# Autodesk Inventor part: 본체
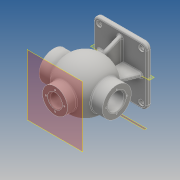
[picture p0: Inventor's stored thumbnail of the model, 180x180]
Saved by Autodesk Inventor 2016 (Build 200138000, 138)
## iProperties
Created: 2017-01
Part Number: 본체
Material: 일반
Document SubType Name: Modeling
Designer: Administrator
Density: 1 g/cm^3
Appearance: 기본값
Author: Administrator
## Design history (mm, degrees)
sketch "스케치1"
  geometry: L1 (57.5, 62.5)-(-57.5, 62.5); L2 (-57.5, 62.5)-(-57.5, -62.5); L3 (-57.5, -62.5)-(57.5, -62.5); L4 (57.5, -62.5)-(57.5, 62.5); L5 (57.5, 62.5)-(-57.5, -62.5); L6 (-57.5, 62.5)-(57.5, -62.5); 1 further point
  constraints: 12 end point, 2 midpoint, 2 parallel, 1 horizontal, 1 perpendicular
  dimensions: "d0" = 125 distance between parallel lines of L3 L1; "d1" = 115 distance between parallel lines of L2 L4
extrude "돌출1" new body sketch "스케치1" distance "d2" = 10; taper "d3" = 0 deg
fillet "모깎기2" dims "d5" = 3
fillet "모깎기3" dims "d6" = 12
node "작업 평면1"
sketch "스케치5"
  geometry: L1 (113.5, -75)-(-22.5, -75); L2 (113.5, -75)-(113.5, -106); L3 (-22.5, -75)-(-22.5, -106); L4 (45.5, 0)-(45.5, -185.881); L5 (113.5, -106)-(88.488, -106); L6 (-22.5, -106)-(2.512, -106); L7 (113.5, -92.5)-(84.778, -92.5); L8 (-22.5, -92.5)-(-6.5, -92.5); L9 (-6.5, -92.5)-(-6.5, -93.5); L10 (-6.5, -93.5)-(-4.75, -93.5); L11 (-4.75, -93.5)-(-4.75, -92.5); L12 (-4.75, -92.5)-(6.222, -92.5); L13 (0, 10)-(91, 10) reference; A1 r 53 centre (45.5, -75) between (2.512, -106) and (88.488, -106); A2 r 43 centre (45.5, -75) between (6.222, -92.5) and (84.778, -92.5)
  constraints: 24 end point, 5 horizontal, 4 point on circle, 4 point on line, 3 perpendicular, 3 vertical, 2 centre point, 1 coincident, 1 midpoint
  dimensions: "d22" = 136 distance between parallel lines of L3 L2; "d27" = 31 distance from line of L2.end L1; "d30" = 53 radius of A1; "d31" = 43 radius of A2; "d32" = 16 distance between parallel lines of L9 L3; "d33" = 17.5 distance between parallel lines of L1 L8; "d34" = 18.5 distance between parallel lines of L1 L10; "d35" = 17.5 distance between parallel lines of L7 L1; "d36" = 17.5 distance from line of L1 L12.end; "d37" = 31 distance between parallel lines of L6 L1; "d38" = 1.75 distance between parallel lines of L11 L9; "d39" = 85 distance between parallel lines of L13 L1
revolve "회전1" sketch "스케치5" stored, may be unused: angle "d40" = 90 deg
sketch "스케치6" dims "d41" = 48
  geometry: 3 further points
  constraints: 1 vertical alignment, 2 other
hole "구멍2" sketch "스케치6" at (0, -24) diameter "d42" = 3.242; stored, may be unused: countersink angle "d46" = 90 deg, drill point angle "d48" = 118 deg; dims "d43" = 16, "d44" = 12, "d45" = 3, "d47" = 19
node "작업 평면2"
sketch "스케치8"
  geometry: C1 r 27 at (0, 0); 1 further point
  constraints: 1 centre point, 1 coincident
  dimensions: "d61" = 54 diameter of C1
extrude "돌출2" join sketch "스케치8" stored distance "d62" = 10; taper "d63" = 0 deg
sketch "스케치9"
  geometry: C1 r 13 at (0, 0); 1 further point
  constraints: 1 centre point, 1 coincident
  dimensions: "d64" = 26 diameter of C1
extrude "돌출3" cut sketch "스케치9" distance "d65" = 50; taper "d66" = 0 deg
sketch "스케치10"
  geometry: A1 r 20 centre (0, 0) between (0, -20) and (0, 20); 3 further points
  constraints: 4 point on circle, 1 centre point, 1 coincident
  dimensions: "d67" = 40 diameter of A1
hole "구멍3" sketch "스케치10" at (0, -20), (20, 0), (0, 20), (-20, 0) diameter "d68" = 3.242; stored, may be unused: countersink angle "d72" = 90 deg, drill point angle "d74" = 118 deg; dims "d69" = 9, "d70" = 12, "d71" = 3, "d73" = 11
fillet "모깎기4" dims "d86" = 3
fillet "모깎기5" dims "d87" = 3
fillet "모깎기6" dims "d88" = 3
sketch "스케치13"
  geometry: A1 r 9 centre (45.5, 50.5) between (54.5, 50.5) and (45.5, 59.5) reference; 2 further points
  constraints: 1 coincident
hole "구멍4" sketch "스케치13" at (45.5, 50.5) diameter "d89" = 8; stored, may be unused: countersink angle "d93" = 90 deg, drill point angle "d95" = 118 deg; dims "d90" = 9, "d91" = 12, "d92" = 3, "d94" = 11
sketch "스케치14"
  geometry: L1 (47.5, 0)-(33.719, -34.109); L2 (-33.719, -34.109)-(-47.5, 0); L3 (51.5, 0)-(39.5, 0) reference; L4 (45.5, 0)-(-45.5, 0) reference; L5 (-39.5, 0)-(-51.5, 0) reference; L6 (-57.5, 3)-(-57.5, 7) reference; L7 (57.5, 7)-(57.5, 3) reference; A1 r 53 centre (0, -75) between (-42.113, -107.179) and (-42.113, -42.821) reference; 1 further point
  constraints: 4 end point, 2 point on circle, 2 point on line
  dimensions: "d102" = 10 distance from line of L6 L2.end; "d103" = 10 distance from line of L7 L1.start; "d104" = 22 deg angle of L1 L7; "d105" = 22 deg angle of L6 L2
extrude "돌출4" join sketch "스케치14" stored distance "d106" = 8; taper "d107" = 0 deg
sketch "스케치15"
  geometry: L1 (-35.992, 37.958)-(0, 52.5); L2 (0, 50.5)-(0, -50.5) reference; L3 (7, 62.5)-(3, 62.5) reference; 1 further point
  constraints: 2 end point, 1 point on line
  dimensions: "d108" = 10 distance from line of L3 L1.end; "d109" = 22 deg angle of L3 L1
feature "리브1" sketch "스케치15" dims "d110" = 1, "d111" = 8, "d112" = 0, "d113" = 0, "d114" = 1, "d115" = 1
sketch "스케치16"
  geometry: L1 (-35.514, -35.354)-(6.924, -52.5); L2 (3, -62.5)-(7, -62.5) reference; A1 r 53 centre (-75, 0) between (-119.753, -28.393) and (-119.753, 28.393) reference; 1 further point
  constraints: 2 end point, 1 point on circle
  dimensions: "d116" = 10 distance from line of L1.end L2; "d117" = 22 deg angle of L1 L2
feature "리브2" sketch "스케치16" dims "d118" = 1, "d119" = 8, "d120" = 0, "d121" = 0, "d122" = 1, "d123" = 1
fillet "모깎기7" dims "d124" = 3
fillet "모깎기8" dims "d125" = 3
sketch "스케치17"
  geometry: A1 r 22.5 centre (0, 0) between (0, -22.5) and (-22.5, 0); 3 further points
  constraints: 4 point on circle, 1 centre point
  dimensions: "d126" = 45 diameter of A1
hole "구멍5" sketch "스케치17" at (0, -22.5), (-22.5, 0), (0, 22.5), (22.5, 0) diameter "d127" = 3.242; stored, may be unused: countersink angle "d131" = 90 deg, drill point angle "d133" = 118 deg; dims "d128" = 12, "d129" = 12, "d130" = 3, "d132" = 15
node "작업 평면3"
sketch "스케치18"
  geometry: L1 (66.425, -140.002)-(24.575, -140.002); L2 (24.575, -140.002)-(24.575, -133.998); L3 (24.575, -133.998)-(66.425, -133.998); L4 (66.425, -133.998)-(66.425, -140.002); L5 (18.5, -147)-(72.5, -147) reference; 3 further points
  constraints: 2 midpoint, 2 other
  dimensions: "d136" = 10 distance from line of point (24.575, -137) L5; "d137" = 27 horizontal distance of L5.start point (45.5, -140.002)
feature "엠보싱1" sketch "스케치18" dims "d0" = 125, "d1" = 115, "d138" = 0.5, "d139" = 0
node "솔리드1"
pattern_linear "직사각형 패턴1" dims "d98" = 91, "d101" = 101
pattern_circular "원형 패턴2" dims angle "d141" = 360 deg
other parameters: "d134" = 38
